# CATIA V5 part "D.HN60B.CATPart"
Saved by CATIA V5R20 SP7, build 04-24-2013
Part number: D.HN60B
Material "Nessuno"
Bounding box of the stored display mesh (mm): x 0 to 150.807, y -124.685 to 0, z -91.151 to 75.737
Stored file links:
  C:\Users\designer2\Desktop\Ottobre 2022\25-10-2022\04\Yori Evo 48V\D.HN60B.CATPart
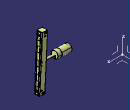
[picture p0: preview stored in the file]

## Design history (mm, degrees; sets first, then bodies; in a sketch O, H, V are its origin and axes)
AxisSystem1: origin (0, 0, 0), X (1, 0, 0), Y (0, 1, 0), Z (0, 0, 1)
Set1
  DatumSurface1
Body1 (main body), material "Nessuno"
